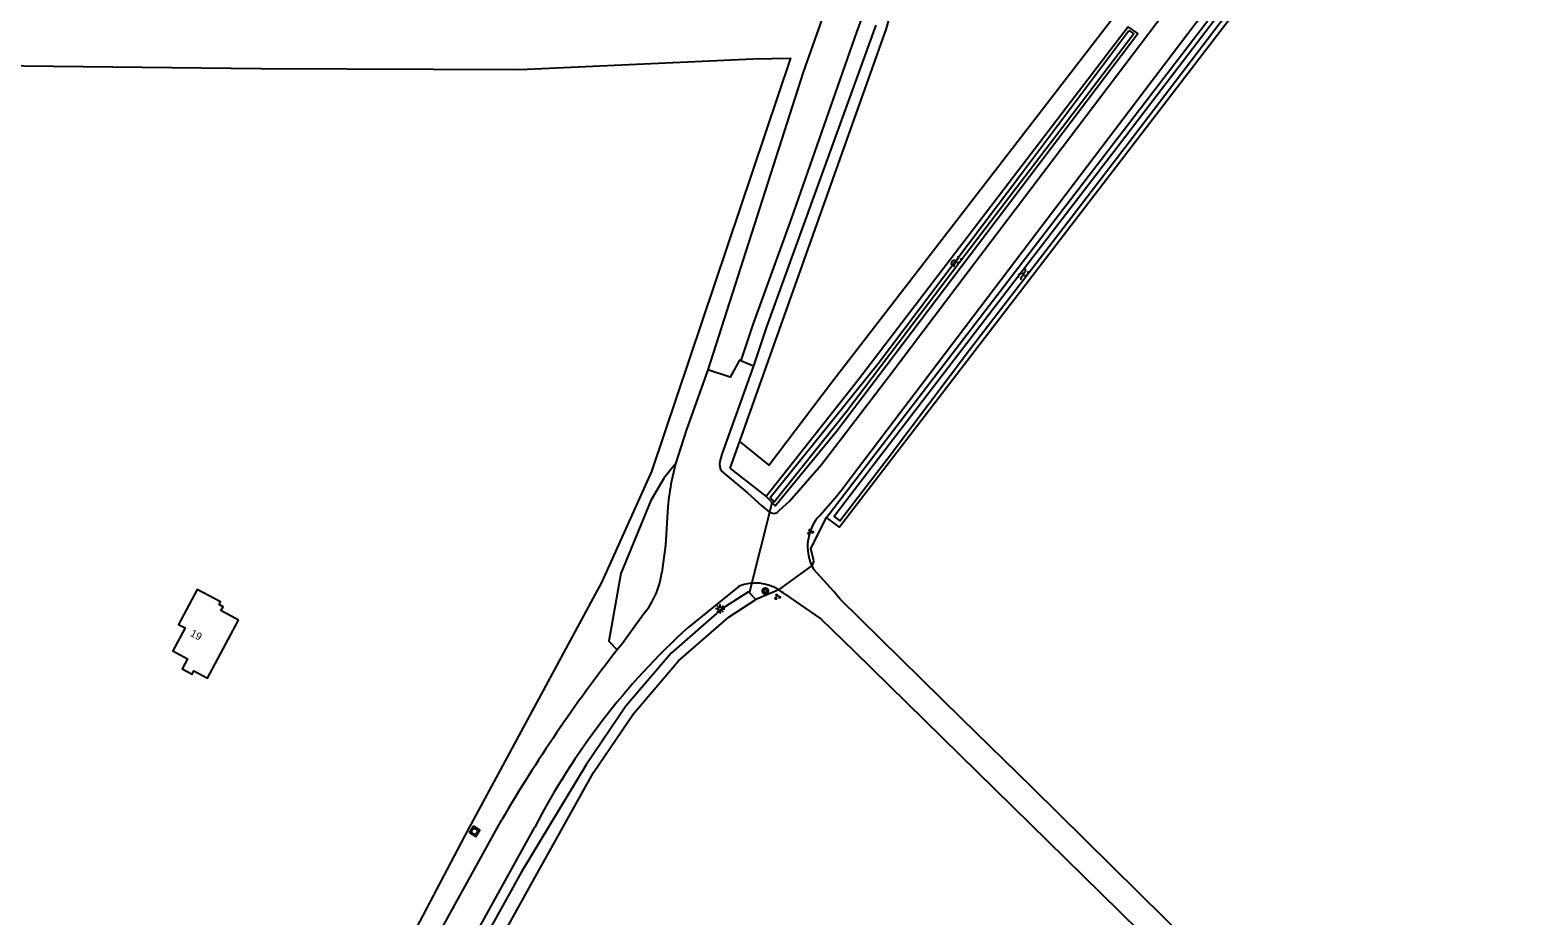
# Model space of a CAD drawing. Extents: x 133000 to 136000, y 400500 to 403500.
# Drawn here: x 134381.4 to 134583, y 401611.2 to 401729.6 of the extents above; entities that cross this region are included whole.
import ezdxf

# ---------------------------------------------------------------- set-up
doc = ezdxf.new("R2010")
doc.units = 0
for name, color, linetype in [('gg-afsc-hekwerk', 7, 'Continuous'), ('gg-anno-huisnummerreeks BGT', 7, 'Continuous'), ('gg-bbg-gedigitaliseerde bebouwing', 7, 'Continuous'), ('gg-knt-onverhard', 7, 'Continuous'), ('gg-knt-verharding', 7, 'Continuous'), ('gg-knt-verharding nz', 7, 'Continuous'), ('gg-kntw-bovenkant insteek waterloop', 7, 'Continuous'), ('gg-kntw-waterlijn', 7, 'Continuous'), ('gg-kwrk-duiker nz buis', 7, 'Continuous'), ('gt-grn-groengrens', 7, 'Continuous'), ('gt-grn-weggrens', 7, 'Continuous'), ('gt-symb-boom', 7, 'Continuous'), ('gt-symb-groenvak', 7, 'Continuous'), ('gt-symb-lichtmast', 7, 'Continuous'), ('gt-symb-rioolschacht', 7, 'Continuous'), ('gt-symb-watersymbool', 7, 'Continuous')]:
    doc.layers.add(name, color=color, linetype=linetype)

# ---------------------------------------------------------------- blocks, each defined once
blk = doc.blocks.new('gt0-WA')
at = {"layer": 'gt-symb-watersymbool'}
for centre, start, end in [((-0.32, 0.02), 28.0725, 151.9275), ((0.43, 0.42), 208.0725, 331.9275), ((-0.32, -0.43), 28.0725, 151.9275), ((0.43, -0.03), 208.0725, 331.9275)]:
    blk.add_arc(centre, 0.425, start, end, dxfattribs=at)
blk = doc.blocks.new('gt0-LMAST')
at = {"layer": 'gt-symb-lichtmast'}
for p, q in [((-0.18, 0.17), (-0.45, 0.44)), ((-0.01, 0.25), (-0.01, 0.62)), ((0.17, 0.17), (0.44, 0.44)), ((-0.26, 0), (-0.63, 0)), ((-0.18, -0.18), (-0.45, -0.45)), ((-0.01, -0.25), (-0.01, -0.63)), ((0.44, -0.45), (0.17, -0.18)), ((0.24, 0), (0.62, 0))]:
    blk.add_line(p, q, dxfattribs=at)
blk.add_circle((-0.01, 0), 0.25, dxfattribs=at)
blk = doc.blocks.new('gt0-GRVAK')
at = {"layer": 'gt-symb-groenvak'}
for p, q in [((-0.11, 0.19), (-0.23, 0.24)), ((-0.18, 0.15), (0.09, 0.15)), ((-0.09, 0.21), (-0.16, 0.32)), ((-0.05, 0.21), (-0.05, 0.39)), ((0, 0.21), (0.06, 0.32)), ((0.01, 0.19), (0.13, 0.24)), ((0.26, -0.05), (0.2, 0.06)), ((0.3, -0.05), (0.3, 0.13)), ((0.35, -0.05), (0.41, 0.06)), ((-0.25, -0.23), (-0.36, -0.18)), ((-0.32, -0.26), (-0.05, -0.26)), ((-0.23, -0.21), (-0.29, -0.1)), ((-0.18, -0.2), (-0.18, -0.02)), ((-0.14, -0.21), (-0.07, -0.1)), ((-0.12, -0.23), (0, -0.18)), ((0.24, -0.07), (0.12, -0.02)), ((0.17, -0.11), (0.44, -0.11)), ((0.37, -0.07), (0.49, -0.02))]:
    blk.add_line(p, q, dxfattribs=at)
blk = doc.blocks.new('gt0-BOOM')
at = {"layer": 'gt-symb-boom'}
for radius in [0.4, 0.2]:
    blk.add_circle((0, 0), radius, dxfattribs=at)
blk = doc.blocks.new('gt0-RS')
at = {"layer": 'gt-symb-rioolschacht'}
blk.add_lwpolyline([(-0.5, -0.5), (0.5, -0.5), (0.5, 0.5), (-0.5, 0.5)], close=True, dxfattribs=at)
blk.add_circle((0, 0), 0.375, dxfattribs=at)

msp = doc.modelspace()

# ---------------------------------------------------------------- linework, layer by layer
at = {"layer": 'gg-afsc-hekwerk'}
msp.add_lwpolyline([(134478.09, 401725.8), (134483.09, 401725.88), (134464.48, 401670.61), (134457.86, 401655.85), (134439.49, 401621.84), (134392.49, 401532.45)], dxfattribs=at)
msp.add_lwpolyline([(134478.09, 401725.8), (134483.09, 401725.88), (134464.48, 401670.61), (134457.86, 401655.85), (134439.49, 401621.84), (134392.49, 401532.45)], dxfattribs=at)
at = {"layer": 'gg-bbg-gedigitaliseerde bebouwing'}
msp.add_lwpolyline([(134409.25, 401650.74), (134406.92, 401652), (134407.21, 401652.52), (134406.67, 401652.81), (134406.86, 401653.16), (134403.75, 401654.83), (134401.24, 401650.16), (134402.12, 401649.69), (134400.47, 401646.62), (134402.44, 401645.55), (134401.74, 401644.24), (134403.07, 401643.51), (134403.3, 401643.95), (134405.11, 401642.98), (134409.25, 401650.74)], dxfattribs=at)
at = {"layer": 'gg-knt-onverhard'}
msp.add_line((134484.78, 401723.99), (134472.01, 401684.18), dxfattribs=at)
msp.add_lwpolyline([(134492.62, 401746.4), (134487.03, 401730.41), (134484.78, 401723.99)], dxfattribs=at)
at = {"layer": 'gg-knt-verharding'}
for p, q in [((134491.21, 401669.84), (134556.33, 401755.72)), ((134467.7, 401671.61), (134467.17, 401669.31)), ((134476.24, 401655.28), (134469.39, 401649.76)), ((134482.27, 401654.24), (134487.16, 401650.9)), ((134489.71, 401653.55), (134505.95, 401637.58)), ((134487.16, 401650.9), (134491.57, 401646.64)), ((134491.57, 401646.64), (134524.54, 401614.27)), ((134390.95, 401527.03), (134444.34, 401623.8)), ((134394.72, 401525.02), (134448.88, 401623.04)), ((134444.34, 401623.8), (134444.47, 401624.04)), ((134524.54, 401614.27), (134559.45, 401579.98))]:
    msp.add_line(p, q, dxfattribs=at)
for points in [[(134481.6, 401665.43), (134482.94, 401666.65), (134487.23, 401671.52), (134496.24, 401683.32), (134506.83, 401697.36), (134552.94, 401758.17)], [(134492.52, 401731.04), (134491.93, 401729.36), (134483.19, 401704.41), (134478.04, 401690.25), (134476.45, 401685.46)], [(134494.48, 401730.29), (134479.86, 401689.97), (134478.15, 401684.72)], [(134476.45, 401685.46), (134476.25, 401685.5), (134475.02, 401683.24), (134472.01, 401684.18)], [(134478.15, 401684.72), (134473.92, 401672.94), (134473.64, 401671.92)], [(134472.01, 401684.18), (134469.18, 401676.24), (134467.7, 401671.61)], [(134467.7, 401671.61), (134466.19, 401669.76), (134464.39, 401666.71), (134460.41, 401656.98), (134458.8, 401647.9), (134459.9, 401646.74)], [(134473.8, 401670.69), (134477.35, 401667.77), (134479.27, 401666.03), (134480.31, 401665.13)], [(134466.69, 401665.91), (134466.38, 401660.76), (134465.88, 401657.1)], [(134463.75, 401651.94), (134462.38, 401650.11), (134460.64, 401647.59), (134459.9, 401646.74)], [(134583.02, 401561.16), (134572.4, 401572.05), (134515.4, 401628.34), (134505.95, 401637.58)]]:
    msp.add_lwpolyline(points, dxfattribs=at)
for centre, radius, start, end in [((134475.61, 401671.55), 2, 169.3408, 205.4703), ((134506.7, 401662.09), 40.19, 169.6458, 174.538), ((134438.89, 401708.63), 65.13, 317.2132, 323.449), ((134480.79, 401666.01), 1, 241.7031, 324.6492), ((134491.52, 401660.59), 6.15, 141.8639, 204.9858), ((134455.53, 401658.35), 10.42, 322.0428, 353.1512), ((134491.35, 401660.49), 5.95, 204.8476, 210.2816), ((134434.03, 401607.66), 72.16, 39.493, 43.682), ((134478.38, 401649.69), 5.99, 58.3983, 110.9486), ((134478.34, 401649.63), 6.05, 49.5783, 58.3213), ((134534.07, 401578.89), 95.95, 132.3872, 152.6075), ((134621.13, 401520.57), 204.73, 141.9526, 149.6415)]:
    msp.add_arc(centre, radius, start, end, dxfattribs=at)
at = {"layer": 'gg-knt-verharding nz'}
msp.add_line((134476.45, 401685.46), (134478.15, 401684.72), dxfattribs=at)
at = {"layer": 'gg-kntw-bovenkant insteek waterloop'}
msp.add_line((134487.91, 401664.47), (134546.24, 401740.51), dxfattribs=at)
for points in [[(134547.18, 401738.14), (134489.65, 401663.14), (134487.91, 401664.47)], [(134479.83, 401667.27), (134481.03, 401666), (134489.3, 401676.06), (134529.55, 401729.19), (134528.25, 401730.08)], [(134528.25, 401730.08), (134492.08, 401682.79), (134479.83, 401667.27)], [(134478.43, 401653.47), (134477.46, 401654.53), (134473.92, 401652.25), (134467.12, 401646.33), (134461.06, 401639.22), (134455.78, 401631.39), (134447.1, 401617.06), (134389.56, 401513.27), (134391.21, 401512.26)], [(134411.81, 401549.41), (134448.75, 401616.05), (134456.75, 401630.34), (134462.04, 401638.16), (134468.1, 401645.28), (134474.9, 401651.19), (134478.43, 401653.47)]]:
    msp.add_lwpolyline(points, dxfattribs=at)
at = {"layer": 'gg-kntw-waterlijn'}
for points in [[(134549.78, 401743.83), (134546.27, 401739.52), (134526.75, 401713.91), (134492.37, 401669.09), (134488.92, 401664.59), (134489.67, 401664.01), (134496.14, 401672.45), (134507.14, 401687.05), (134518.15, 401701.37), (134528.85, 401715.3), (134549.7, 401742.67), (134550.33, 401743.5), (134549.78, 401743.83)], [(134528.34, 401729.58), (134528.99, 401729.14), (134515.12, 401710.93), (134505.83, 401698.71), (134490.51, 401678.55), (134480.88, 401666.52), (134480.38, 401667.14), (134485.97, 401674.08), (134494.82, 401685.06), (134501.67, 401694.12), (134513.9, 401710.3), (134528.34, 401729.58)]]:
    msp.add_lwpolyline(points, dxfattribs=at)
at = {"layer": 'gg-kwrk-duiker nz buis'}
msp.add_line((134477.58, 401654.4), (134480.65, 401666.41), dxfattribs=at)
at = {"layer": 'gt-grn-groengrens'}
for p, q in [((134476.26, 401674.64), (134474.98, 401671.06)), ((134474.98, 401671.06), (134479.83, 401667.27)), ((134486.2, 401658.64), (134485.95, 401657.99)), ((134481.52, 401654.78), (134478.43, 401653.47))]:
    msp.add_line(p, q, dxfattribs=at)
for points in [[(134503.34, 401757.41), (134495.88, 401729.85), (134476.26, 401674.64)], [(134532.59, 401739.56), (134517.39, 401719.83), (134488.43, 401682.3), (134480.25, 401671.47), (134476.26, 401674.64)], [(134376.54, 401724.87), (134412.27, 401724.49), (134446.87, 401724.36), (134478.09, 401725.8)], [(134486.2, 401658.64), (134485.8, 401660.29), (134487.91, 401664.47)]]:
    msp.add_lwpolyline(points, dxfattribs=at)
at = {"layer": 'gt-grn-weggrens'}
msp.add_line((134481.52, 401654.78), (134485.95, 401657.99), dxfattribs=at)

# ---------------------------------------------------------------- block references
at = {"layer": 'gt-symb-boom'}
msp.add_blockref('gt0-BOOM', (134479.72, 401654.63), dxfattribs=at)
at = {"layer": 'gt-symb-groenvak'}
for p in [(134485.74, 401662.54), (134481.31, 401653.86)]:
    msp.add_blockref('gt0-GRVAK', p, dxfattribs=at)
at = {"layer": 'gt-symb-lichtmast'}
msp.add_blockref('gt0-LMAST', (134473.68, 401652.23), dxfattribs=at)
at = {"layer": 'gt-symb-rioolschacht', "rotation": -122.29094835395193}
msp.add_blockref('gt0-RS', (134440.83, 401622.5), dxfattribs=at)
at = {"layer": 'gt-symb-watersymbool'}
for p, rotation in [((134505.21, 401698.65), 52.55716365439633), ((134514.17, 401696.91), 52.47682811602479)]:
    msp.add_blockref('gt0-WA', p, dxfattribs=dict(at, rotation=rotation))

# ---------------------------------------------------------------- texts
at = {"layer": 'gg-anno-huisnummerreeks BGT'}
msp.add_text('19', height=1, rotation=331.9, dxfattribs=at).set_placement((134402.73, 401648.67))

doc.saveas('drawing.dxf')
